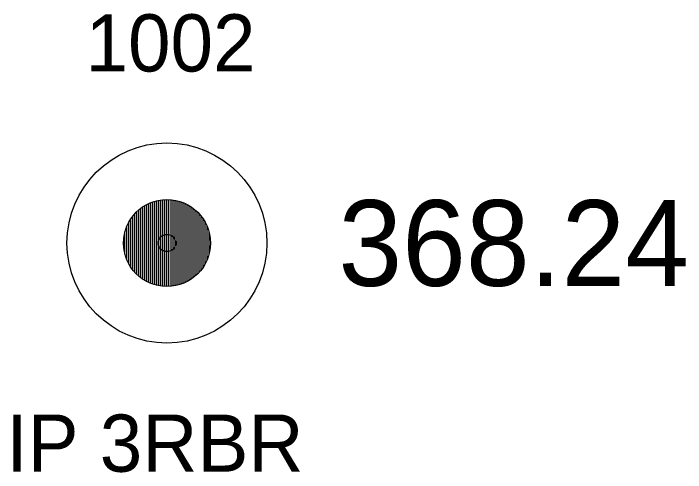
# Model space of a CAD drawing. Extents: x 2231119 to 2232595, y 1035731 to 1037094.
# Drawn here: x 2232583.65 to 2232595.41, y 1037001.2 to 1037009.23 of the extents above; entities that cross this region are included whole.
import ezdxf

# ---------------------------------------------------------------- set-up
doc = ezdxf.new("R2010")
doc.units = 0
for name, color, linetype in [('RD_EX_DV_Prop_txCode', 7, 'Continuous'), ('RD_EX_DV_PropPin', 7, 'Continuous'), ('RD_EX_TX_DV_Prop_ELEV', 7, 'Continuous'), ('RD_SMD_Locator', 7, 'Continuous')]:
    doc.layers.add(name, color=color, linetype=linetype)

msp = doc.modelspace()

# ---------------------------------------------------------------- linework, layer by layer
at = {"layer": 'RD_EX_DV_PropPin'}
for p, q in [((2232585.953, 1037004.563), (2232585.953, 1037005.875)), ((2232585.988, 1037004.543), (2232585.988, 1037005.895)), ((2232586.023, 1037004.526), (2232586.023, 1037005.912)), ((2232586.058, 1037004.511), (2232586.058, 1037005.927)), ((2232586.093, 1037004.499), (2232586.093, 1037005.939)), ((2232586.128, 1037004.488), (2232586.128, 1037005.95)), ((2232586.163, 1037004.478), (2232586.163, 1037005.96)), ((2232586.198, 1037004.471), (2232586.198, 1037005.967)), ((2232586.233, 1037004.465), (2232586.233, 1037005.973)), ((2232586.268, 1037004.461), (2232586.268, 1037005.977)), ((2232586.303, 1037004.459), (2232586.303, 1037005.979)), ((2232586.338, 1037004.458), (2232586.338, 1037005.98)), ((2232586.373, 1037004.459), (2232586.373, 1037005.979)), ((2232586.409, 1037004.461), (2232586.409, 1037005.977)), ((2232586.444, 1037004.465), (2232586.444, 1037005.973)), ((2232586.479, 1037004.471), (2232586.479, 1037005.967)), ((2232586.514, 1037004.478), (2232586.514, 1037005.96)), ((2232586.549, 1037004.488), (2232586.549, 1037005.95)), ((2232586.584, 1037004.499), (2232586.584, 1037005.939)), ((2232586.619, 1037004.511), (2232586.619, 1037005.927)), ((2232586.654, 1037004.526), (2232586.654, 1037005.912)), ((2232586.689, 1037004.543), (2232586.689, 1037005.895)), ((2232586.724, 1037004.563), (2232586.724, 1037005.875)), ((2232585.813, 1037004.668), (2232585.813, 1037005.77)), ((2232585.848, 1037004.637), (2232585.848, 1037005.801)), ((2232585.883, 1037004.609), (2232585.883, 1037005.829)), ((2232585.918, 1037004.584), (2232585.918, 1037005.854)), ((2232586.759, 1037004.584), (2232586.759, 1037005.854)), ((2232586.794, 1037004.609), (2232586.794, 1037005.829)), ((2232586.829, 1037004.637), (2232586.829, 1037005.801)), ((2232586.864, 1037004.668), (2232586.864, 1037005.77)), ((2232585.708, 1037004.792), (2232585.708, 1037005.646)), ((2232585.743, 1037004.745), (2232585.743, 1037005.693)), ((2232585.778, 1037004.704), (2232585.778, 1037005.734)), ((2232586.899, 1037004.704), (2232586.899, 1037005.734)), ((2232586.934, 1037004.745), (2232586.934, 1037005.693)), ((2232586.969, 1037004.792), (2232586.969, 1037005.646)), ((2232585.673, 1037004.849), (2232585.673, 1037005.589)), ((2232587.004, 1037004.849), (2232587.004, 1037005.589)), ((2232585.603, 1037005.023), (2232585.603, 1037005.415)), ((2232585.638, 1037004.921), (2232585.638, 1037005.517)), ((2232587.039, 1037004.921), (2232587.039, 1037005.517)), ((2232587.074, 1037005.023), (2232587.074, 1037005.415))]:
    msp.add_line(p, q, dxfattribs=at)
for radius in [1.75, 0.761]:
    msp.add_circle((2232586.338, 1037005.219), radius, dxfattribs=at)
at = {"layer": 'RD_SMD_Locator'}
msp.add_circle((2232586.339, 1037005.219), 0.15, dxfattribs=at)

# ---------------------------------------------------------------- texts
at = {"layer": 'RD_EX_DV_Prop_txCode'}
for s, p in [('1002', (2232584.913, 1037008.219)), ('IP 3RBR', (2232583.527, 1037001.219))]:
    msp.add_text(s, height=1, dxfattribs=at).set_placement(p)
at = {"layer": 'RD_EX_TX_DV_Prop_ELEV'}
msp.add_text('368.24', height=1.5, dxfattribs=at).set_placement((2232589.339, 1037004.469))

doc.saveas('drawing.dxf')
